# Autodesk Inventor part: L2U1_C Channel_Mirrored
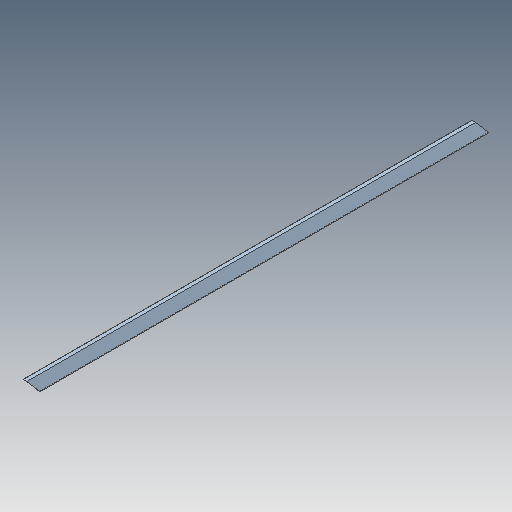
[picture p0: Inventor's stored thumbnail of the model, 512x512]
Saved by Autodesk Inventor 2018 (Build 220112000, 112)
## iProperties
Created: 2018-02
Part Number: L2U1_C Channel_Mirrored
Material: Steel, Mild
Document SubType Name: Modeling
Designer: STK
Density: 7.85 g/cm^3
Appearance: Semi-Polished
Author: STK
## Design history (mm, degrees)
derived "L2U1_C Channel.ipt"
feature "Solid1::L2U1_C Channel.ipt" dims "d0" = 10
tag "TaggingFeature1"
body "Solid1"
